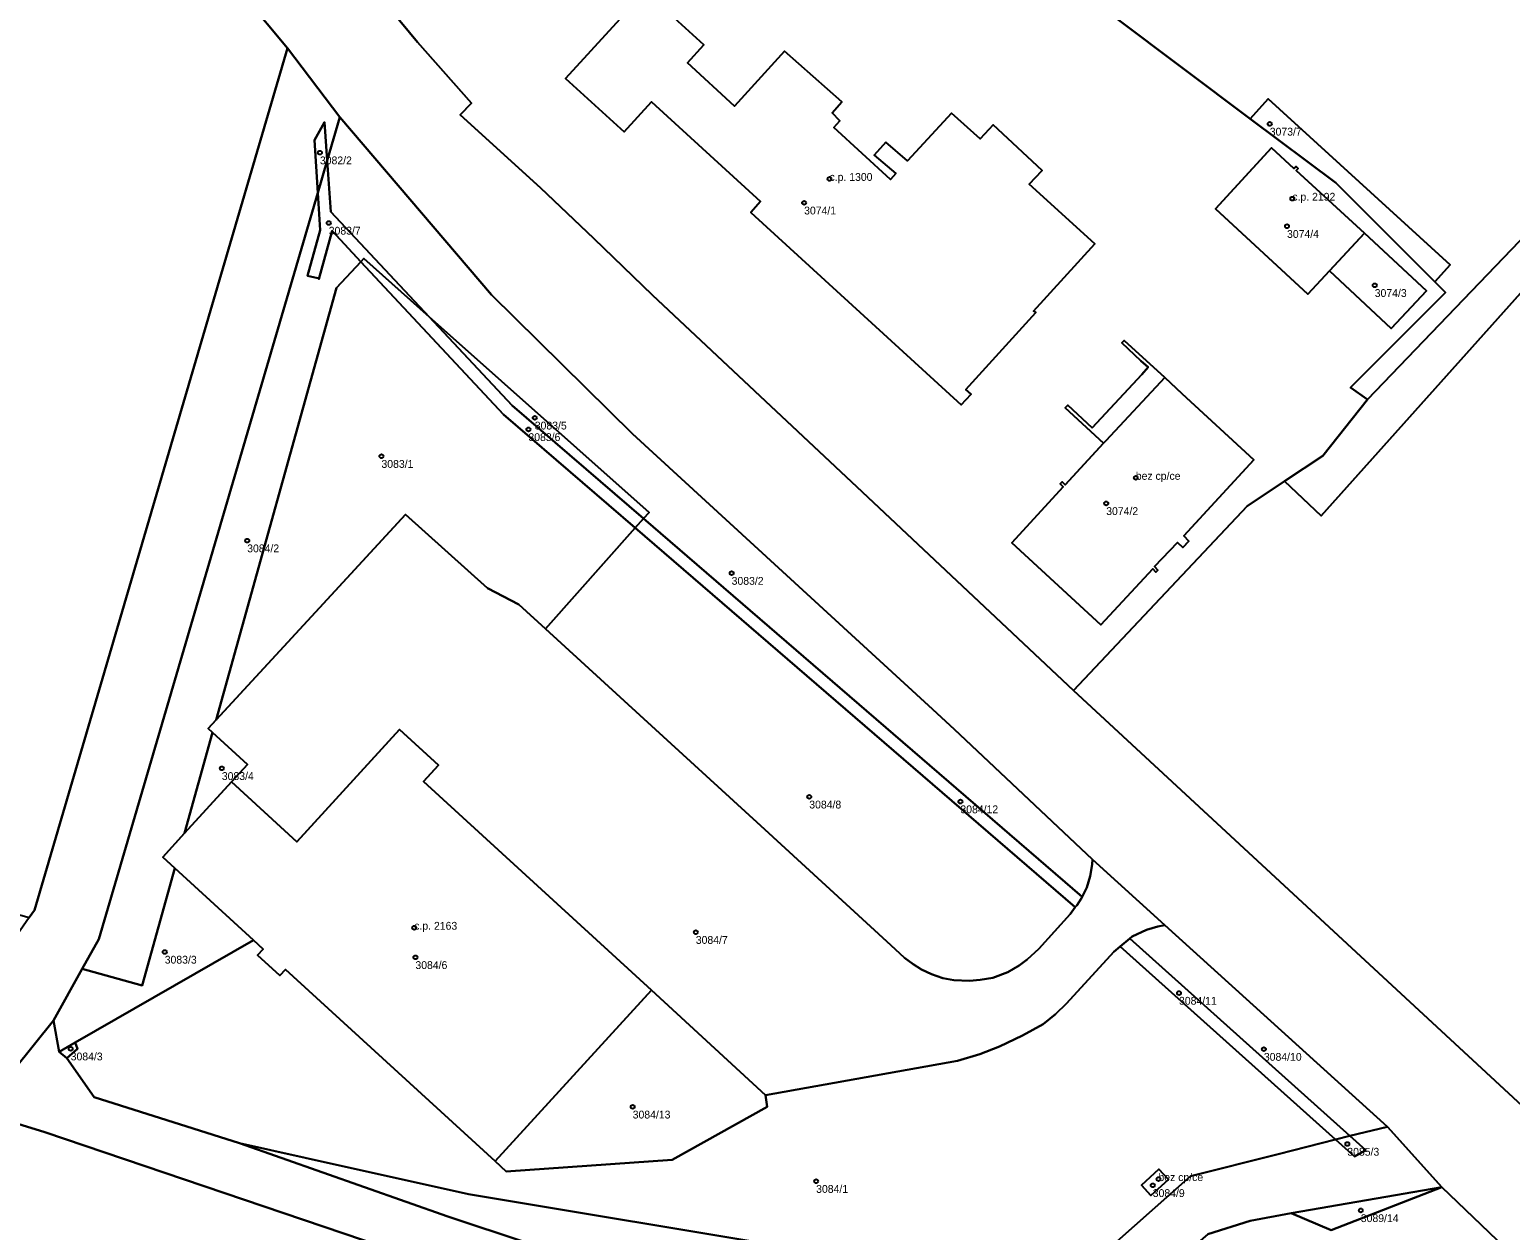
# Model space of a CAD drawing. Extents: x -878211 to -870363, y -1058464 to -1052522.
# Drawn here: x -873599.2 to -873409.6, y -1056881.9 to -1056728.2 of the extents above; entities that cross this region are included whole.
import ezdxf

# ---------------------------------------------------------------- set-up
doc = ezdxf.new("R2010")
doc.units = 0
for name, color, linetype in [('Vrstva 50', 7, 'Continuous'), ('Vrstva 51', 7, 'Continuous'), ('Vrstva 52', 7, 'Continuous')]:
    doc.layers.add(name, color=color, linetype=linetype)

msp = doc.modelspace()

# ---------------------------------------------------------------- linework, layer by layer
at = {"layer": 'Vrstva 50'}
for centre in [(-873440.39, -1056740.24994), (-873562.01, -1056743.92994), (-873496.76, -1056747.28994), (-873500.01, -1056750.34994), (-873437.5, -1056749.81994), (-873560.88, -1056752.92994), (-873438.18, -1056753.34994), (-873426.95, -1056760.90994), (-873535.31, -1056779.35994), (-873534.5, -1056777.87994), (-873554.13, -1056782.78994), (-873457.54, -1056785.55994), (-873461.33, -1056788.82994), (-873571.32, -1056793.59994), (-873509.29, -1056797.75994), (-873574.57, -1056822.74994), (-873499.35, -1056826.39994), (-873480, -1056827.00994), (-873549.93, -1056843.15994), (-873513.88, -1056843.72994), (-873581.88, -1056846.25994), (-873549.78, -1056846.94994), (-873452.01, -1056851.51994), (-873593.92, -1056858.64994), (-873441.14, -1056858.69994), (-873521.96, -1056866.08994), (-873430.46, -1056870.84994), (-873498.47, -1056875.60994), (-873455.37, -1056876.13994), (-873454.64, -1056875.33994), (-873428.73, -1056879.34994)]:
    msp.add_circle(centre, 0.25, dxfattribs=at)
at = {"layer": 'Vrstva 51'}
for points in [[(-873313.02, -1056957.72), (-873404.07, -1056869.66), (-873465.5, -1056812.78), (-873493.25, -1056786.72), (-873519.41, -1056762.17), (-873526.95, -1056754.9), (-873533.76, -1056748.44), (-873544.05, -1056739.09), (-873542.58, -1056737.57), (-873549.53, -1056729.78), (-873552.78, -1056725.8), (-873554.8, -1056723.33), (-873571.06, -1056702.12), (-873580.47, -1056689.83), (-873605.91, -1056656.2)], [(-873613.41, -1056671.16), (-873577.01, -1056717.52), (-873566.17, -1056730.55), (-873559.44, -1056739.37), (-873540.05, -1056762.14), (-873521.98, -1056779.94), (-873484.09, -1056814.7), (-873480.78, -1056817.74), (-873463.07, -1056834.4), (-873453.82, -1056842.82), (-873425.32, -1056868.63), (-873418.37, -1056876.37), (-873410.29, -1056884.08)], [(-873232.23, -1056767.27), (-873305.14, -1056681.91), (-873344.63, -1056694.63), (-873332.3, -1056707.57), (-873344.87, -1056720.24), (-873357.36, -1056707.09), (-873375.09, -1056724.84), (-873433.81, -1056790.41), (-873438.51, -1056785.99), (-873443.29, -1056789.18), (-873465.5, -1056812.78), (-873404.07, -1056869.66), (-873313.02, -1056957.72), (-873275.37, -1056992.33), (-873244.08, -1057017.52), (-873241.04, -1057016.22), (-873237, -1057015.07), (-873232.85, -1057014.45)], [(-873552.78, -1056725.8), (-873549.53, -1056729.78), (-873542.58, -1056737.57), (-873544.05, -1056739.09), (-873533.76, -1056748.44), (-873526.95, -1056754.9), (-873519.41, -1056762.17), (-873493.25, -1056786.72), (-873465.5, -1056812.78), (-873443.29, -1056789.18), (-873438.51, -1056785.99), (-873433.61, -1056782.72), (-873427.89, -1056775.53), (-873430.07, -1056773.98), (-873417.88, -1056761.83), (-873419.26, -1056760.45), (-873431.94, -1056747.81), (-873442.88, -1056739.6), (-873460.22, -1056726.58)], [(-873626.7, -1056882.66), (-873617.6, -1056877.37), (-873606.95, -1056866.33), (-873601.14, -1056861.31), (-873596.12, -1056855.04), (-873592.44, -1056848.42), (-873590.31, -1056844.6), (-873562.29, -1056749.09), (-873562.72, -1056742.33), (-873561.41, -1056740.01), (-873561.07, -1056744.93), (-873559.44, -1056739.37), (-873566.17, -1056730.55), (-873598.56, -1056840.89), (-873599.24, -1056841.86), (-873608.69, -1056855.43), (-873616.51, -1056863.22), (-873624.79, -1056871.46), (-873629.81, -1056874.32), (-873631.97, -1056875.55), (-873710.5, -1056920.91)], [(-873459.99, -1056883.33), (-873450.53, -1056874.96), (-873439.33, -1056872.15), (-873431.97, -1056870.28), (-873459.53, -1056845.56), (-873460.36, -1056846.24), (-873466.4, -1056852.86), (-873467.84, -1056854.24), (-873469.41, -1056855.49), (-873472.04, -1056856.97), (-873475, -1056858.38), (-873477.5, -1056859.34), (-873480.37, -1056860.2), (-873504.96, -1056864.59), (-873504.74, -1056866.08), (-873516.9, -1056872.87), (-873538.17, -1056874.36), (-873539.59, -1056873.05), (-873566.42, -1056848.5), (-873567.13, -1056849.28), (-873569.99, -1056846.67), (-873569.26, -1056845.88), (-873570.52, -1056844.73), (-873593.36, -1056857.86), (-873593.07, -1056858.68), (-873594.42, -1056859.84), (-873590.93, -1056864.85), (-873572.29, -1056870.75), (-873563.91, -1056872.62), (-873542.99, -1056877.28), (-873500.67, -1056884.31)], [(-873504.85, -1056893.67), (-873545.61, -1056880.12), (-873572.29, -1056870.75), (-873590.93, -1056864.85), (-873594.42, -1056859.84), (-873595.4, -1056859.03), (-873596.12, -1056855.04), (-873601.14, -1056861.31), (-873606.95, -1056866.33), (-873597.25, -1056869.34), (-873543.71, -1056887.47)], [(-873543.71, -1056887.47), (-873597.25, -1056869.34), (-873606.95, -1056866.33), (-873617.6, -1056877.37), (-873626.7, -1056882.66)], [(-873448.31, -1056882.37), (-873442.92, -1056880.68), (-873437.64, -1056879.7), (-873418.37, -1056876.37), (-873425.32, -1056868.63), (-873430.13, -1056869.81), (-873428.07, -1056871.65), (-873429.55, -1056872.46), (-873431.97, -1056870.28), (-873439.33, -1056872.15), (-873450.53, -1056874.96), (-873459.99, -1056883.33)]]:
    msp.add_lwpolyline(points, dxfattribs=at)
for points in [[(-873613.41, -1056671.16), (-873617.79, -1056665.35), (-873622.44, -1056661.75), (-873624.32, -1056663.56), (-873654.8, -1056704.21), (-873657.13, -1056707.03), (-873672.39, -1056722.83), (-873693.16, -1056731.44), (-873710.35, -1056729.19), (-873718.92, -1056728.98), (-873716.41, -1056732.97), (-873713.77, -1056781.79), (-873714.37, -1056830.96), (-873715.94, -1056830.96), (-873698.72, -1056860.89), (-873616.81, -1056858.72), (-873604.63, -1056840.36), (-873599.24, -1056841.86), (-873598.56, -1056840.89), (-873566.17, -1056730.55), (-873577.01, -1056717.52)], [(-873417.29, -1056758.29), (-873419.26, -1056760.45), (-873417.88, -1056761.83), (-873430.07, -1056773.98), (-873427.89, -1056775.53), (-873377.68, -1056723.21), (-873427.81, -1056691), (-873450.96, -1056706.77), (-873464.59, -1056716.88), (-873460.71, -1056721.65), (-873460.22, -1056726.58), (-873442.88, -1056739.6), (-873440.58, -1056737.04)], [(-873438.51, -1056785.99), (-873433.81, -1056790.41), (-873375.09, -1056724.84), (-873357.36, -1056707.09), (-873360.45, -1056703.3), (-873377.68, -1056723.21), (-873427.89, -1056775.53), (-873433.61, -1056782.72)], [(-873419.26, -1056760.45), (-873417.29, -1056758.29), (-873440.58, -1056737.04), (-873442.88, -1056739.6), (-873431.94, -1056747.81)], [(-873480.78, -1056817.74), (-873484.09, -1056814.7), (-873521.98, -1056779.94), (-873540.05, -1056762.14), (-873559.44, -1056739.37), (-873561.07, -1056744.93), (-873560.62, -1056751.51), (-873548, -1056764.96), (-873519.87, -1056790.01), (-873520.56, -1056790.78), (-873464.4, -1056839.19), (-873463.83, -1056838), (-873463.4, -1056836.55), (-873463.12, -1056835.07), (-873463.07, -1056834.4)], [(-873561.07, -1056744.93), (-873561.41, -1056740.01), (-873562.72, -1056742.33), (-873562.29, -1056749.09)], [(-873548, -1056764.96), (-873560.62, -1056751.51), (-873561.07, -1056744.93), (-873562.29, -1056749.09), (-873561.99, -1056753.85), (-873563.62, -1056759.69), (-873562.28, -1056760), (-873562.15, -1056760.12), (-873560.46, -1056753.95), (-873556.77, -1056757.9), (-873556.39, -1056757.49)], [(-873428.28, -1056754.23), (-873437.01, -1056746.22), (-873436.75, -1056745.94), (-873437.03, -1056745.68), (-873437.29, -1056745.96), (-873440.15, -1056743.33), (-873447.32, -1056751.13), (-873435.5, -1056762.06), (-873432.73, -1056759.06)], [(-873432.73, -1056759.06), (-873435.5, -1056762.06), (-873447.32, -1056751.13), (-873440.15, -1056743.33), (-873437.29, -1056745.96), (-873437.03, -1056745.68), (-873436.75, -1056745.94), (-873437.01, -1056746.22), (-873428.28, -1056754.23), (-873420.33, -1056761.62), (-873424.84, -1056766.46)], [(-873575.75, -1056818.17), (-873576.32, -1056817.64), (-873575.29, -1056816.52), (-873559.88, -1056761.24), (-873556.77, -1056757.9), (-873560.46, -1056753.95), (-873562.15, -1056760.12), (-873562.28, -1056760), (-873563.62, -1056759.69), (-873561.99, -1056753.85), (-873562.29, -1056749.09), (-873590.31, -1056844.6), (-873592.44, -1056848.42), (-873584.77, -1056850.55), (-873580.58, -1056835.53), (-873582.13, -1056834.11), (-873579.34, -1056831.06)], [(-873428.28, -1056754.23), (-873432.73, -1056759.06), (-873424.84, -1056766.46), (-873420.33, -1056761.62)], [(-873556.77, -1056757.9), (-873559.88, -1056761.24), (-873575.29, -1056816.52), (-873562.57, -1056802.76), (-873551.04, -1056790.24), (-873540.57, -1056799.69), (-873536.55, -1056801.76), (-873533.13, -1056804.89), (-873521.63, -1056791.98), (-873538.49, -1056777.45)], [(-873520.56, -1056790.78), (-873537.38, -1056776.28), (-873548, -1056764.96), (-873556.39, -1056757.49), (-873556.77, -1056757.9), (-873538.49, -1056777.45), (-873521.63, -1056791.98)], [(-873537.38, -1056776.28), (-873520.56, -1056790.78), (-873519.87, -1056790.01), (-873548, -1056764.96)], [(-873463.13, -1056779.14), (-873456.79, -1056772.31), (-873455.98, -1056771.41), (-873456.9, -1056770.58), (-873459.35, -1056768.28), (-873459.03, -1056767.96), (-873453.82, -1056772.73), (-873451.6, -1056774.82), (-873442.44, -1056783.27), (-873451.4, -1056792.99), (-873450.76, -1056793.65), (-873451.52, -1056794.46), (-873452.22, -1056793.85), (-873455.15, -1056796.93), (-873454.72, -1056797.36), (-873454.96, -1056797.62), (-873455.38, -1056797.22), (-873462.04, -1056804.36), (-873473.4, -1056793.86), (-873466.83, -1056786.71), (-873467.24, -1056786.32), (-873466.98, -1056786.08), (-873466.57, -1056786.45), (-873461.69, -1056781.12), (-873466.58, -1056776.58), (-873466.26, -1056776.24)], [(-873463.13, -1056779.14), (-873466.26, -1056776.24), (-873466.58, -1056776.58), (-873461.69, -1056781.12), (-873466.57, -1056786.45), (-873466.98, -1056786.08), (-873467.24, -1056786.32), (-873466.83, -1056786.71), (-873473.4, -1056793.86), (-873462.04, -1056804.36), (-873455.38, -1056797.22), (-873454.96, -1056797.62), (-873454.72, -1056797.36), (-873455.15, -1056796.93), (-873452.22, -1056793.85), (-873451.52, -1056794.46), (-873450.76, -1056793.65), (-873451.4, -1056792.99), (-873442.44, -1056783.27), (-873451.6, -1056774.82), (-873453.82, -1056772.73), (-873459.03, -1056767.96), (-873459.35, -1056768.28), (-873456.9, -1056770.58), (-873455.98, -1056771.41), (-873456.79, -1056772.31)], [(-873453.82, -1056842.82), (-873463.07, -1056834.4), (-873463.12, -1056835.07), (-873463.4, -1056836.55), (-873463.83, -1056838), (-873464.4, -1056839.19), (-873464.48, -1056839.37), (-873465.11, -1056840.32), (-873465.29, -1056840.54), (-873465.96, -1056841.4), (-873469.96, -1056845.86), (-873471.45, -1056847.21), (-873472.48, -1056847.99), (-873473.92, -1056848.83), (-873475.85, -1056849.55), (-873477.46, -1056849.83), (-873478.83, -1056849.97), (-873480.83, -1056849.89), (-873482.24, -1056849.6), (-873483.72, -1056849.08), (-873484.99, -1056848.49), (-873486.05, -1056847.82), (-873487.14, -1056846.99), (-873488.89, -1056845.37), (-873505.56, -1056830.12), (-873521.06, -1056815.94), (-873533.13, -1056804.89), (-873536.55, -1056801.76), (-873540.57, -1056799.69), (-873551.04, -1056790.24), (-873562.57, -1056802.76), (-873575.29, -1056816.52), (-873576.32, -1056817.64), (-873575.75, -1056818.17), (-873571.28, -1056822.27), (-873573.32, -1056824.48), (-873564.95, -1056832.15), (-873551.81, -1056817.77), (-873546.82, -1056822.34), (-873548.73, -1056824.44), (-873519.55, -1056851.14), (-873504.96, -1056864.59), (-873480.37, -1056860.2), (-873477.5, -1056859.34), (-873475, -1056858.38), (-873472.04, -1056856.97), (-873469.41, -1056855.49), (-873467.84, -1056854.24), (-873466.4, -1056852.86), (-873460.36, -1056846.24), (-873459.53, -1056845.56), (-873458.29, -1056844.55), (-873457.99, -1056844.3), (-873456.19, -1056843.42), (-873454.74, -1056842.99)], [(-873465.29, -1056840.54), (-873521.63, -1056791.98), (-873533.13, -1056804.89), (-873521.06, -1056815.94), (-873505.56, -1056830.12), (-873488.89, -1056845.37), (-873487.14, -1056846.99), (-873486.05, -1056847.82), (-873484.99, -1056848.49), (-873483.72, -1056849.08), (-873482.24, -1056849.6), (-873480.83, -1056849.89), (-873478.83, -1056849.97), (-873477.46, -1056849.83), (-873475.85, -1056849.55), (-873473.92, -1056848.83), (-873472.48, -1056847.99), (-873471.45, -1056847.21), (-873469.96, -1056845.86), (-873465.96, -1056841.4)], [(-873464.4, -1056839.19), (-873520.56, -1056790.78), (-873521.63, -1056791.98), (-873465.29, -1056840.54), (-873465.11, -1056840.32), (-873464.48, -1056839.37)], [(-873539.59, -1056873.05), (-873519.55, -1056851.14), (-873548.73, -1056824.44), (-873546.82, -1056822.34), (-873551.81, -1056817.77), (-873564.95, -1056832.15), (-873573.32, -1056824.48), (-873579.34, -1056831.06), (-873582.13, -1056834.11), (-873580.58, -1056835.53), (-873570.52, -1056844.73), (-873569.26, -1056845.88), (-873569.99, -1056846.67), (-873567.13, -1056849.28), (-873566.42, -1056848.5)], [(-873573.32, -1056824.48), (-873571.28, -1056822.27), (-873575.75, -1056818.17), (-873579.34, -1056831.06)], [(-873593.36, -1056857.86), (-873570.52, -1056844.73), (-873580.58, -1056835.53), (-873584.77, -1056850.55), (-873592.44, -1056848.42), (-873596.12, -1056855.04), (-873595.4, -1056859.03)], [(-873425.32, -1056868.63), (-873453.82, -1056842.82), (-873454.74, -1056842.99), (-873456.19, -1056843.42), (-873457.99, -1056844.3), (-873458.29, -1056844.55), (-873430.13, -1056869.81)], [(-873431.97, -1056870.28), (-873430.13, -1056869.81), (-873458.29, -1056844.55), (-873459.53, -1056845.56)], [(-873539.59, -1056873.05), (-873538.17, -1056874.36), (-873516.9, -1056872.87), (-873504.74, -1056866.08), (-873504.96, -1056864.59), (-873519.55, -1056851.14)], [(-873593.36, -1056857.86), (-873595.4, -1056859.03), (-873594.42, -1056859.84), (-873593.07, -1056858.68)], [(-873428.07, -1056871.65), (-873430.13, -1056869.81), (-873431.97, -1056870.28), (-873429.55, -1056872.46)], [(-873498.48, -1056892.32), (-873477.16, -1056891.76), (-873461.89, -1056885.15), (-873459.99, -1056883.33), (-873500.67, -1056884.31), (-873542.99, -1056877.28), (-873563.91, -1056872.62), (-873572.29, -1056870.75), (-873545.61, -1056880.12), (-873504.85, -1056893.67), (-873498.09, -1056893.57)], [(-873453.37, -1056875.41), (-873455.6, -1056877.44), (-873456.81, -1056876.1), (-873454.59, -1056874.07)], [(-873453.37, -1056875.41), (-873454.59, -1056874.07), (-873456.81, -1056876.1), (-873455.6, -1056877.44)], [(-873410.29, -1056884.08), (-873418.37, -1056876.37), (-873432.53, -1056881.88), (-873437.64, -1056879.7), (-873442.92, -1056880.68), (-873448.31, -1056882.37), (-873456.43, -1056889.44), (-873458.74, -1056892.34), (-873444.99, -1056892.03), (-873416.53, -1056885.51)], [(-873418.37, -1056876.37), (-873437.64, -1056879.7), (-873432.53, -1056881.88)]]:
    msp.add_lwpolyline(points, close=True, dxfattribs=at)
at = {"layer": 'Vrstva 52'}
for points in [[(-873489.54, -1056742.57), (-873491.06, -1056744.26), (-873488.25, -1056746.58), (-873488.95, -1056747.37), (-873496.2, -1056740.72), (-873495.45, -1056739.87), (-873496.43, -1056738.84), (-873495.2, -1056737.41), (-873502.52, -1056730.95), (-873508.93, -1056737.97), (-873514.95, -1056732.42), (-873512.85, -1056730.12), (-873520.36, -1056723.26), (-873530.57, -1056734.44), (-873523.07, -1056741.26), (-873519.57, -1056737.4), (-873505.61, -1056750.2), (-873506.84, -1056751.58), (-873479.91, -1056776.22), (-873478.63, -1056774.83), (-873479.29, -1056774.24), (-873470.35, -1056764.4), (-873470.63, -1056764.21), (-873462.8, -1056755.62), (-873471.19, -1056747.94), (-873469.54, -1056746.23), (-873475.82, -1056740.38), (-873477.49, -1056742.16), (-873481.12, -1056738.87), (-873486.78, -1056744.97)], [(-873447.32, -1056751.13), (-873435.5, -1056762.06), (-873432.73, -1056759.06), (-873428.28, -1056754.23), (-873437.01, -1056746.22), (-873436.75, -1056745.94), (-873437.03, -1056745.68), (-873437.29, -1056745.96), (-873440.15, -1056743.33)], [(-873442.44, -1056783.27), (-873451.6, -1056774.82), (-873453.82, -1056772.73), (-873461.39, -1056780.81), (-873461.69, -1056781.12), (-873466.57, -1056786.45), (-873466.98, -1056786.08), (-873467.24, -1056786.32), (-873466.83, -1056786.71), (-873473.4, -1056793.86), (-873462.04, -1056804.36), (-873455.38, -1056797.22), (-873454.96, -1056797.62), (-873454.72, -1056797.36), (-873455.15, -1056796.93), (-873452.22, -1056793.85), (-873451.52, -1056794.46), (-873450.76, -1056793.65), (-873451.4, -1056792.99)], [(-873582.13, -1056834.11), (-873580.58, -1056835.53), (-873570.52, -1056844.73), (-873569.26, -1056845.88), (-873569.99, -1056846.67), (-873567.13, -1056849.28), (-873566.42, -1056848.5), (-873539.59, -1056873.05), (-873519.55, -1056851.14), (-873548.73, -1056824.44), (-873546.82, -1056822.34), (-873551.81, -1056817.77), (-873564.95, -1056832.15), (-873573.32, -1056824.48), (-873579.34, -1056831.06)], [(-873456.81, -1056876.1), (-873455.6, -1056877.44), (-873453.37, -1056875.41), (-873454.59, -1056874.07)]]:
    msp.add_lwpolyline(points, close=True, dxfattribs=at)

# ---------------------------------------------------------------- texts
at = {"layer": 'Vrstva 50'}
for s, p in [('3073/7', (-873440.39, -1056741.739)), ('3082/2', (-873562.01, -1056745.419)), ('c.p. 1300', (-873496.76, -1056747.54)), ('c.p. 2192', (-873437.5, -1056750.07)), ('3074/1', (-873500.01, -1056751.839)), ('3083/7', (-873560.88, -1056754.419)), ('3074/4', (-873438.18, -1056754.839)), ('3074/3', (-873426.95, -1056762.399)), ('3083/5', (-873534.5, -1056779.369)), ('3083/6', (-873535.31, -1056780.849)), ('3083/1', (-873554.13, -1056784.279)), ('bez cp/ce', (-873457.54, -1056785.81)), ('3074/2', (-873461.33, -1056790.319)), ('3084/2', (-873571.32, -1056795.089)), ('3083/2', (-873509.29, -1056799.249)), ('3083/4', (-873574.57, -1056824.239)), ('3084/8', (-873499.35, -1056827.889)), ('3084/12', (-873480, -1056828.499)), ('c.p. 2163', (-873549.93, -1056843.409)), ('3084/7', (-873513.88, -1056845.219)), ('3083/3', (-873581.88, -1056847.749)), ('3084/6', (-873549.78, -1056848.439)), ('3084/11', (-873452.01, -1056853.009)), ('3084/3', (-873593.92, -1056860.139)), ('3084/10', (-873441.14, -1056860.189)), ('3084/13', (-873521.96, -1056867.579)), ('3085/3', (-873430.46, -1056872.339)), ('bez cp/ce', (-873454.64, -1056875.59)), ('3084/1', (-873498.47, -1056877.099)), ('3084/9', (-873455.37, -1056877.629)), ('3089/14', (-873428.73, -1056880.839))]:
    msp.add_text(s, height=0.999996, dxfattribs=at).set_placement(p)

doc.saveas('drawing.dxf')
